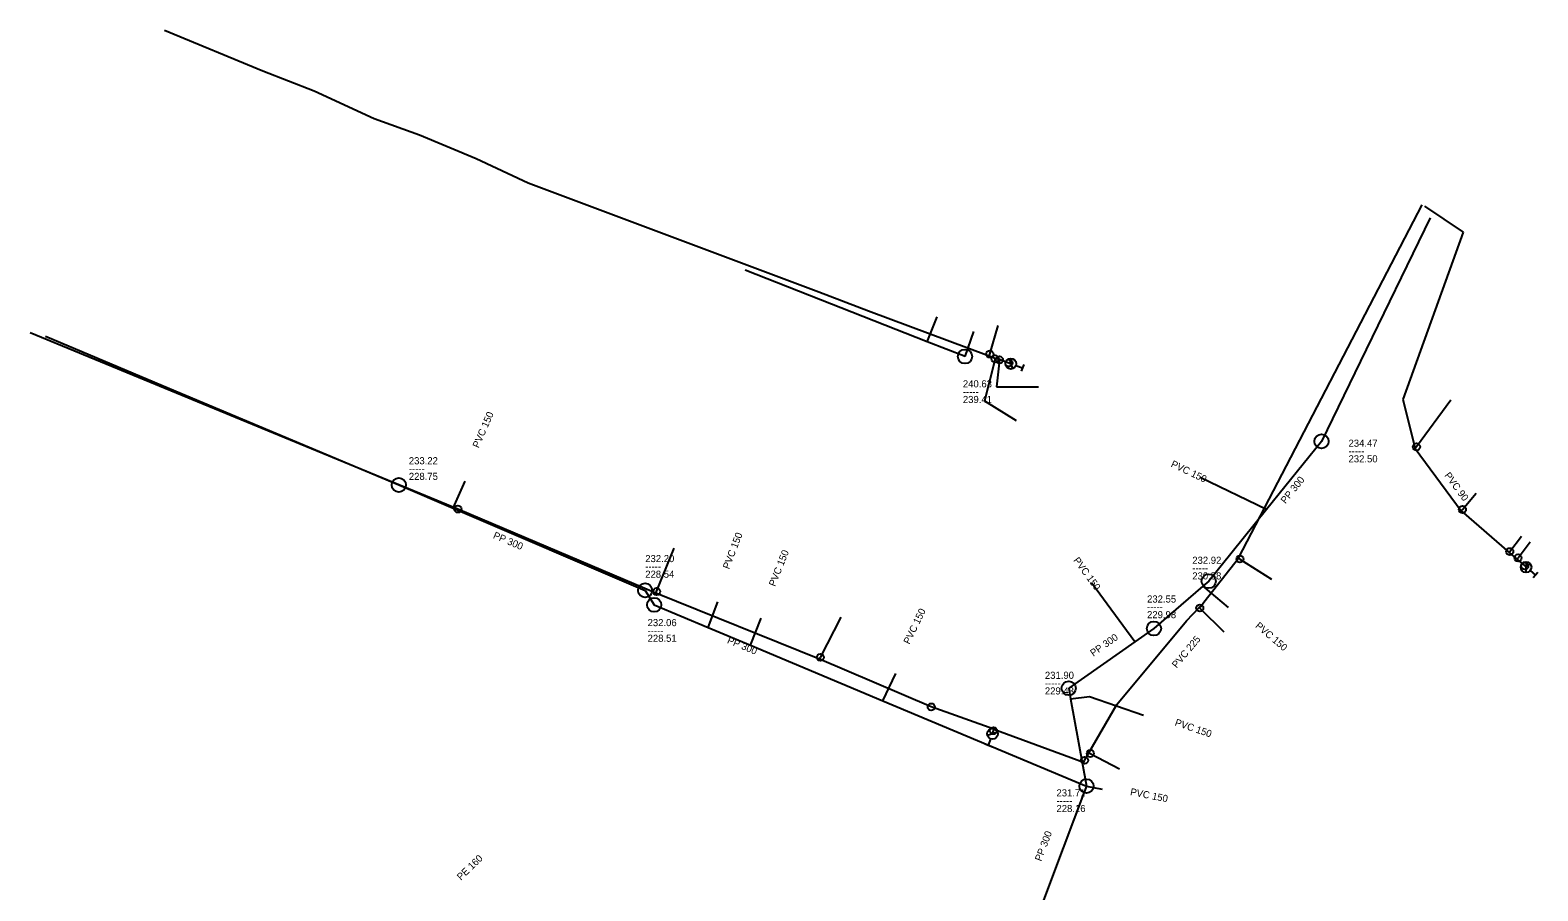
# Model space of a CAD drawing. Extents: x -771212 to -769571, y -1050452 to -1050119.
# Drawn here: x -770919.1 to -770706.9, y -1050239.8 to -1050118.7 of the extents above; entities that cross this region are included whole.
import ezdxf

# ---------------------------------------------------------------- set-up
doc = ezdxf.new("R2010")
doc.units = 0
doc.layers.add('Level 0', color=7, linetype='Continuous')

msp = doc.modelspace()

# ---------------------------------------------------------------- linework, layer by layer
at = {"layer": 'Level 0'}
for p, q in [((-770900.21, -1050118.68), (-770886.36, -1050124.38)), ((-770886.36, -1050124.38), (-770879.16, -1050127.21)), ((-770879.16, -1050127.21), (-770870.71, -1050131.11)), ((-770870.71, -1050131.11), (-770864.32, -1050133.39)), ((-770864.32, -1050133.39), (-770856.34, -1050136.72)), ((-770856.34, -1050136.72), (-770849.05, -1050140.16)), ((-770849.05, -1050140.16), (-770808.14, -1050155.48)), ((-770749.09, -1050192.94), (-770723.23, -1050143.26)), ((-770722.09, -1050145.07), (-770731.91, -1050165.25)), ((-770722.9, -1050143.43), (-770717.45, -1050147.11)), ((-770717.45, -1050147.11), (-770725.96, -1050170.62)), ((-770792.88, -1050162.5), (-770818.5, -1050152.44)), ((-770808.14, -1050155.48), (-770801.14, -1050158.14)), ((-770801.14, -1050158.14), (-770784.14, -1050164.47)), ((-770792.88, -1050162.5), (-770791.46, -1050159)), ((-770858.93, -1050186.05), (-770919.12, -1050161.25)), ((-770916.96, -1050161.73), (-770899.52, -1050169.07)), ((-770787.56, -1050164.59), (-770786.34, -1050161.07)), ((-770784.07, -1050164.25), (-770782.89, -1050160.23)), ((-770787.56, -1050164.59), (-770792.88, -1050162.5)), ((-770784.14, -1050164.47), (-770784.07, -1050164.25)), ((-770783.32, -1050164.92), (-770784.83, -1050170.81)), ((-770784.14, -1050164.47), (-770783.3, -1050164.82)), ((-770783.3, -1050164.82), (-770783.32, -1050164.92)), ((-770783.3, -1050164.82), (-770782.71, -1050164.96)), ((-770782.72, -1050165.06), (-770783.14, -1050168.86)), ((-770782.71, -1050164.96), (-770782.72, -1050165.06)), ((-770782.71, -1050164.96), (-770781.38, -1050165.5)), ((-770781.38, -1050165.5), (-770781.12, -1050165.6)), ((-770781.35, -1050164.89), (-770780.89, -1050166.31)), ((-770780.42, -1050165.86), (-770779.48, -1050166.2)), ((-770779.3, -1050165.73), (-770779.65, -1050166.67)), ((-770731.91, -1050165.25), (-770737.39, -1050176.52)), ((-770899.52, -1050169.07), (-770867.24, -1050182.66)), ((-770783.14, -1050168.86), (-770777.21, -1050168.86)), ((-770725.96, -1050170.62), (-770724.19, -1050177.52)), ((-770784.83, -1050170.81), (-770780.34, -1050173.58)), ((-770719.2, -1050170.74), (-770724.03, -1050177.3)), ((-770737.39, -1050176.52), (-770745.12, -1050186.1)), ((-770724.03, -1050177.3), (-770724.19, -1050177.52)), ((-770724.19, -1050177.52), (-770717.73, -1050186.31)), ((-770867.24, -1050182.66), (-770859.57, -1050185.94)), ((-770859.57, -1050185.94), (-770857.91, -1050182.14)), ((-770745.12, -1050186.1), (-770754.49, -1050181.62)), ((-770717.56, -1050186.11), (-770715.65, -1050183.82)), ((-770859.57, -1050185.94), (-770832.58, -1050197.49)), ((-770831.06, -1050197.89), (-770858.93, -1050186.05)), ((-770745.12, -1050186.1), (-770753.26, -1050196.19)), ((-770717.73, -1050186.31), (-770717.56, -1050186.11)), ((-770717.73, -1050186.31), (-770710.99, -1050192.15)), ((-770830.96, -1050197.65), (-770828.48, -1050191.55)), ((-770710.9, -1050192.03), (-770709.24, -1050189.87)), ((-770709.74, -1050192.91), (-770708.04, -1050190.66)), ((-770753.95, -1050199.13), (-770749.09, -1050192.94)), ((-770749.09, -1050192.94), (-770748.87, -1050193.08)), ((-770748.87, -1050193.08), (-770744.43, -1050195.91)), ((-770710.99, -1050192.15), (-770710.9, -1050192.03)), ((-770710.99, -1050192.15), (-770709.89, -1050193.1)), ((-770709.89, -1050193.1), (-770709.74, -1050192.91)), ((-770709.89, -1050193.1), (-770708.79, -1050194.05)), ((-770708.59, -1050193.47), (-770708.64, -1050194.97)), ((-770708.79, -1050194.05), (-770708.61, -1050194.22)), ((-770708.04, -1050194.7), (-770707.27, -1050195.34)), ((-770706.95, -1050194.96), (-770707.59, -1050195.73)), ((-770832.58, -1050197.49), (-770831.3, -1050199.52)), ((-770831.06, -1050197.89), (-770830.96, -1050197.65)), ((-770808.04, -1050207.14), (-770831.06, -1050197.89)), ((-770763.66, -1050204.73), (-770769.74, -1050196.43)), ((-770754.07, -1050196.89), (-770760.98, -1050202.85)), ((-770753.26, -1050196.19), (-770754.07, -1050196.89)), ((-770754.07, -1050196.89), (-770750.55, -1050199.9)), ((-770831.3, -1050199.52), (-770823.71, -1050202.7)), ((-770823.71, -1050202.7), (-770822.33, -1050199.09)), ((-770756.41, -1050201.77), (-770754.62, -1050199.88)), ((-770754.62, -1050199.88), (-770754.36, -1050199.76)), ((-770754.62, -1050199.88), (-770754.53, -1050199.97)), ((-770754.53, -1050199.97), (-770751.12, -1050203.34)), ((-770754.36, -1050199.76), (-770753.95, -1050199.13)), ((-770817.75, -1050205.2), (-770816.25, -1050201.41)), ((-770807.92, -1050206.91), (-770805.01, -1050201.27)), ((-770766.21, -1050213.53), (-770756.41, -1050201.77)), ((-770823.71, -1050202.7), (-770817.75, -1050205.2)), ((-770760.98, -1050202.85), (-770763.66, -1050204.73)), ((-770817.75, -1050205.2), (-770799.12, -1050213.01)), ((-770763.66, -1050204.73), (-770772.97, -1050211.25)), ((-770808.04, -1050207.14), (-770807.92, -1050206.91)), ((-770792.31, -1050213.88), (-770808.04, -1050207.14)), ((-770799.12, -1050213.01), (-770797.28, -1050209.2)), ((-770799.12, -1050213.01), (-770770.47, -1050225.02)), ((-770772.97, -1050211.25), (-770772.7, -1050212.74)), ((-770772.7, -1050212.74), (-770770.06, -1050212.42)), ((-770772.7, -1050212.74), (-770770.47, -1050225.02)), ((-770770.06, -1050212.42), (-770762.43, -1050215.03)), ((-770783.49, -1050216.99), (-770792.31, -1050213.88)), ((-770770.13, -1050220.32), (-770766.21, -1050213.53)), ((-770783.7, -1050217.67), (-770783.56, -1050217.23)), ((-770783.56, -1050217.23), (-770783.49, -1050216.99)), ((-770783.49, -1050216.99), (-770770.87, -1050221.63)), ((-770783.83, -1050219.49), (-770784.77, -1050219.14)), ((-770782.99, -1050217.44), (-770784.41, -1050217.9)), ((-770783.96, -1050218.37), (-770784.3, -1050219.31)), ((-770770.87, -1050221.63), (-770770.75, -1050221.4)), ((-770770.75, -1050221.4), (-770770.13, -1050220.32)), ((-770770.13, -1050220.32), (-770769.93, -1050220.43)), ((-770769.93, -1050220.43), (-770765.82, -1050222.61)), ((-770770.47, -1050225.02), (-770770.88, -1050226.1)), ((-770770.47, -1050225.02), (-770768.25, -1050225.46)), ((-770770.88, -1050226.1), (-770775.11, -1050237.31)), ((-770775.11, -1050237.31), (-770777.92, -1050244.75))]:
    msp.add_line(p, q, dxfattribs=at)
for centre, radius in [((-770787.56, -1050164.59), 1), ((-770784.07, -1050164.25), 0.5), ((-770783.32, -1050164.92), 0.5), ((-770782.72, -1050165.06), 0.5), ((-770781.38, -1050165.5), 0.5), ((-770781.12, -1050165.6), 0.75), ((-770737.39, -1050176.52), 1), ((-770724.03, -1050177.3), 0.5), ((-770867.24, -1050182.66), 1), ((-770858.93, -1050186.05), 0.5), ((-770717.56, -1050186.11), 0.5), ((-770710.9, -1050192.03), 0.5), ((-770748.87, -1050193.08), 0.5), ((-770709.74, -1050192.91), 0.5), ((-770708.61, -1050194.22), 0.75), ((-770708.79, -1050194.05), 0.5), ((-770753.26, -1050196.19), 1), ((-770832.58, -1050197.49), 1), ((-770830.96, -1050197.65), 0.5), ((-770831.3, -1050199.52), 1), ((-770754.53, -1050199.97), 0.5), ((-770760.98, -1050202.85), 1), ((-770807.92, -1050206.91), 0.5), ((-770772.97, -1050211.25), 1), ((-770792.31, -1050213.88), 0.5), ((-770783.7, -1050217.67), 0.75), ((-770783.56, -1050217.23), 0.5), ((-770770.75, -1050221.4), 0.5), ((-770769.93, -1050220.43), 0.5), ((-770770.47, -1050225.02), 1)]:
    msp.add_circle(centre, radius, dxfattribs=at)

# ---------------------------------------------------------------- texts
for s, p in [('240.63', (-770787.86, -1050168.93)), ('-----', (-770787.86, -1050170.03)), ('239.41', (-770787.86, -1050171.13)), ('234.47', (-770733.59, -1050177.28)), ('233.22', (-770865.83, -1050179.75)), ('-----', (-770733.59, -1050178.38)), ('232.50', (-770733.59, -1050179.48)), ('-----', (-770865.83, -1050180.85)), ('228.75', (-770865.83, -1050181.95)), ('232.20', (-770832.56, -1050193.51)), ('232.92', (-770755.58, -1050193.75)), ('-----', (-770832.56, -1050194.61)), ('228.54', (-770832.56, -1050195.71)), ('-----', (-770755.58, -1050194.85)), ('230.58', (-770755.58, -1050195.95)), ('232.55', (-770761.94, -1050199.2)), ('-----', (-770761.94, -1050200.3)), ('232.06', (-770832.23, -1050202.52)), ('229.98', (-770761.94, -1050201.4)), ('-----', (-770832.23, -1050203.62)), ('228.51', (-770832.23, -1050204.72)), ('-----', (-770776.32, -1050211.03)), ('231.90', (-770776.32, -1050209.93)), ('229.43', (-770776.32, -1050212.13)), ('231.71', (-770774.69, -1050226.47)), ('-----', (-770774.69, -1050227.57)), ('228.16', (-770774.69, -1050228.67))]:
    msp.add_text(s, height=1, dxfattribs=at).set_placement(p)
for s, rotation, p in [('PVC 150', 66.402, (-770856, -1050177.54)), ('PVC 150', 334.447, (-770758.68, -1050180.05)), ('PVC 90', 306.313, (-770720.15, -1050181.32)), ('PP 300', 51.1, (-770742.46, -1050185.37)), ('PP 300', 336.832, (-770854.06, -1050190.11)), ('PVC 150', 69.08, (-770820.76, -1050194.58)), ('PVC 150', 68.407, (-770814.29, -1050197.02)), ('PVC 150', 306.224, (-770772.37, -1050193.27)), ('PVC 150', 64.222, (-770795.38, -1050205.15)), ('PVC 150', 319.466, (-770746.79, -1050202.61)), ('PP 300', 337.244, (-770821.12, -1050204.87)), ('PP 300', 35.049, (-770769.51, -1050206.83)), ('PVC 225', 50.072, (-770757.78, -1050208.5)), ('PVC 150', 341.116, (-770758.11, -1050216.46)), ('PVC 150', 348.789, (-770764.37, -1050226.27)), ('PP 300', 69.326, (-770776.84, -1050235.67)), ('PE 160', 44.021, (-770858.49, -1050238.34))]:
    msp.add_text(s, height=1, rotation=rotation, dxfattribs=at).set_placement(p)

doc.saveas('drawing.dxf')
